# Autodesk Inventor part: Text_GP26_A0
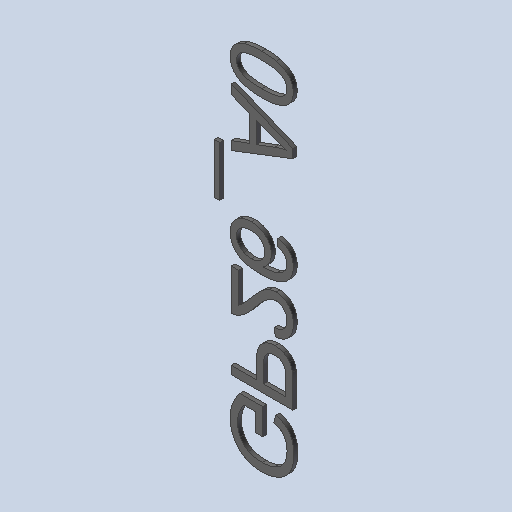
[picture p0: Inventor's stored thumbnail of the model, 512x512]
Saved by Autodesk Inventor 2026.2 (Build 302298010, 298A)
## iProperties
Created: 2026-10
Part Number: Text_GP26_A0
Material: Générique
Document SubType Name: Modeling
Designer: mel
Density: 1 g/cm^3
Appearance: Par défaut
Author: mel
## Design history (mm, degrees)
feature "Base1"
feature "Base2"
feature "Base3"
feature "Base4"
feature "Base5"
feature "Base6"
feature "Base7"
node "Solide1"
node "Solide2"
node "Solide3"
node "Solide4"
node "Solide5"
node "Solide6"
node "Solide7"
